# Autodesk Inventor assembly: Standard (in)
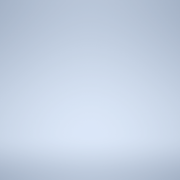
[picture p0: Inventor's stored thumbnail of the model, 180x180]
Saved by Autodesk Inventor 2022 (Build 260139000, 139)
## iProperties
Created: 2021-02
Part Number: Standard (in)
Document SubType Name: Assembly
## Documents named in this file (1)
- C:\Users\ENU\Desktop\New folder for ita\Standard (in).iam
